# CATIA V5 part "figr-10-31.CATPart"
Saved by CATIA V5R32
Part number: Part1
Bounding box of the stored display mesh (mm): x -84 to 53, y -93.367 to 104.555, z -56.529 to 41.172
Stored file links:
  D:\PROJECTS\Project 2022\CATIA V5 6R 2022\Resources\Part Files\c10_catia_v5_6r2022_prt\c10_catia_v5_6r2022_prt\figr-10-31.CATPart
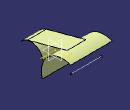
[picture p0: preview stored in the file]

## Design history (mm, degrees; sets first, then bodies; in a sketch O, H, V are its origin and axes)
Body1 (main body)
  Sketch1 on yz-plane, origin (0, 0, 0), H (0, 1, 0), V (0, 0, 1)
    arc A1 centre (-59.8904, -36.5447) radius 41.17 from (-93.3668, -12.5802) to (-23.896, -56.5291) cw
  Extrude1: Element1 Sketch1, Lim1 20, Lim2 42
  Sketch2 on yz-plane, origin (0, 0, 0), H (0, 1, 0), V (0, 0, 1)
    arc A1 centre (78.3128, -29.0048) radius 70.3421 from (104.5554, 36.2588) to (11.1367, -49.8706) ccw
  Extrude2: Element1 Sketch2, Lim1 53, Lim2 84
  Sketch3 on xy-plane, origin (0, 0, 0), H (1, 0, 0), V (0, 1, 0)
    line L1 (-58.0902, 93.9265) -> (40.4277, 93.9265)
    horizontal: L1 H
  Sweep1: type Segment, GuideSurf (Extrude1; Extrude2), Spine Sketch3, Length1 20, Length2 0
